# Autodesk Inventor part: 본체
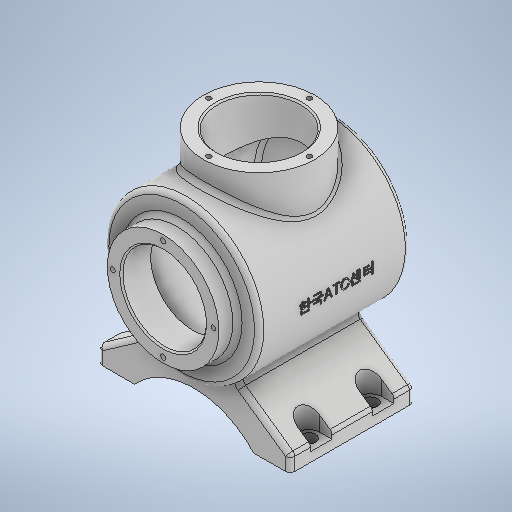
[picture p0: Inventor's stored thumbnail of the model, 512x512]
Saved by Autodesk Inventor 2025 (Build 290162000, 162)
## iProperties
Created: 2024-07
Part Number: 본체
Material: 일반
Document SubType Name: Modeling
Designer: 학생
Density: 1 g/cm^3
Appearance: 기본값
Author: 학생
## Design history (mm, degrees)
sketch "스케치1"
  geometry: C1 r 50 at (0, 0); C2 r 36 at (0, 0); 1 further point
  constraints: 2 centre point, 2 coincident
  dimensions: "d0" = 100 diameter of C1; "d3" = 72 diameter of C2
extrude "돌출1" new body sketch "스케치1" distance "d1" = 108; taper "d2" = 0 deg
fillet "모깎기1" dims "d6" = 3
sketch "스케치2"
  geometry: L1 (-50, -108)-(50, -108) reference; L2 (143.33, 5)-(-131.324, 5); L3 (-47, 0)-(47, 0) reference; L4 (113, 5)-(-113, 5); A1 r 113 centre (0, 5) between (-113, 5) and (113, 5); 2 further points
  constraints: 4 end point, 3 point on circle, 3 point on line, 1 centre point, 1 collinear, 1 midpoint, 1 parallel
  dimensions: "d8" = 113 radius of A1
revolve "회전1" sketch "스케치2" stored, may be unused: angle "d9" = 90 deg
node "작업 평면1"
feature "쉘1" dims "d33" = 7
extrude "돌출5" join sketch "스케치1" distance "d34" = 12; taper "d35" = 0 deg
sketch "스케치3"
  geometry: L1 (0, -237.107)-(0, 83.685); L2 (36, 12)-(-36, 12) reference; C1 r 36 at (0, -50); 1 further point
  constraints: 2 end point, 2 point on line, 1 centre point, 1 vertical
  dimensions: "d11" = 72 diameter of C1; "d37" = 62 distance from line of C1.centre L2
extrude "돌출3" join sketch "스케치3" stored distance "d14" = 50; taper "d15" = 0 deg
fillet "모깎기2" dims "d16" = 3
fillet "모깎기6" dims "d28" = 3
node "작업 평면3"
sketch "스케치5"
  geometry: L1 (0, 68.499)-(0, -75.315); L2 (25.101, -41.102)-(62.088, -67); L3 (62.088, -67)-(62.088, -77); L4 (62.088, -77)-(38.5, -77); L5 (-24.468, -40.658)-(-62.088, -67); L6 (-62.088, -67)-(-62.088, -77); L7 (-62.088, -77)-(-38.5, -77); C1 r 43 at (0, 0) reference; A1 r 52.096 centre (0, -112.096) between (38.5, -77) and (-38.5, -77); A2 r 72.039 centre (0.921, 26.759) between (-24.468, -40.658) and (25.101, -41.102); 2 further points
  constraints: 14 end point, 5 point on circle, 2 centre point, 2 perpendicular, 2 point on line, 2 vertical, 3 other
  dimensions: "d39" = 17 distance from line of L4 point (0, -60); "d40" = 77 distance from line of L4 point (0, 0); "d41" = 10 distance of L2.end L3.end; "d42" = 55 deg angle of L3 L2; "d43" = 77 distance of L4.end L7.end
extrude "돌출6" join sketch "스케치5" distance "d44" = 80; taper "d45" = 0 deg
sketch "스케치6"
  geometry: L1 (-38.5, 42.294)-(-38.5, -123.644); L2 (-124.405, -40)-(51.766, -40); L3 (23.588, 0)-(23.588, -80) reference; L4 (-100.588, 0)-(-100.588, -80) reference; L5 (0, 0)-(23.588, 0) reference; 7 further points
  constraints: 4 end point, 3 midpoint, 2 point on line, 2 symmetric about line, 1 horizontal, 1 vertical
  dimensions: "d53" = 108 distance of point (15.5, -20) point (-92.5, -20); "d54" = 108 distance of point (15.5, -60) point (-92.5, -60); "d55" = 40 distance of point (15.5, -60) point (15.5, -20); "d56" = 20 distance from line of point (15.5, -20) L5
hole "구멍1" sketch "스케치6" at (15.5, -20), (15.5, -60), (-92.5, -20), (-92.5, -60) diameter "d46" = 9; stored, may be unused: countersink angle "d50" = 90 deg, drill point angle "d52" = 0 deg; dims "d47" = 24, "d48" = 4, "d49" = 2, "d51" = 6
sketch "스케치7"
  geometry: C1 r 4.5 at (0, 0) reference; C2 r 4.5 at (0, -40) reference; 3 further points
  constraints: 2 coincident
hole "구멍2" sketch "스케치7" at (0, 0), (0, -40) diameter "d57" = 14; stored, may be unused: countersink angle "d61" = 90 deg, drill point angle "d63" = 0 deg; dims "d58" = 6, "d59" = 4, "d60" = 2, "d62" = 6
sketch "스케치8"
  geometry: C1 r 4.5 at (0, 0) reference; C2 r 4.5 at (0, -40) reference; 3 further points
  constraints: 2 coincident
hole "구멍3" sketch "스케치8" at (0, 0), (0, -40) diameter "d64" = 14; stored, may be unused: countersink angle "d68" = 90 deg, drill point angle "d70" = 0 deg; dims "d65" = 6, "d66" = 4, "d67" = 2, "d69" = 8
sketch "스케치9"
  geometry: L1 (-15.5, -20)-(8.088, -20) reference; L2 (-15.5, -20)-(-15.5, 60) reference; L3 (8.088, 60)-(-15.5, 60) reference; L4 (8.088, -20)-(8.088, 60) reference; L5 (-116.088, -20)-(-92.5, -20) reference; L6 (-116.088, -20)-(-116.088, 60) reference; L7 (-92.5, 60)-(-116.088, 60) reference; L8 (-92.5, -20)-(-92.5, 60) reference; L9 (28.226, -7)-(0, -7); L10 (0, -7)-(0, 7); L11 (0, 7)-(28.226, 7); L12 (28.226, 7)-(28.226, -7); L13 (31.115, 33)-(0, 33); L14 (0, 33)-(0, 47); L15 (0, 47)-(31.115, 47); L16 (31.115, 47)-(31.115, 33); L17 (-108, -7)-(-135.114, -7); L18 (-135.114, -7)-(-135.114, 7); L19 (-135.114, 7)-(-108, 7); L20 (-108, 7)-(-108, -7); L21 (-108, 33)-(-139.115, 33); L22 (-139.115, 33)-(-139.115, 47); L23 (-139.115, 47)-(-108, 47); L24 (-108, 47)-(-108, 33); C1 r 4.5 at (0, 40) reference; C2 r 4.5 at (0, 0) reference; C3 r 4.5 at (-108, 40) reference; C4 r 4.5 at (-108, 0) reference; 5 further points
  constraints: 32 end point, 8 parallel, 4 coincident, 4 horizontal, 4 midpoint, 4 perpendicular
  dimensions: "d73" = 14 distance between parallel lines of L11 L9; "d74" = 14 distance between parallel lines of L15 L13; "d75" = 14 distance between parallel lines of L19 L17; "d76" = 14 distance between parallel lines of L23 L21
extrude "돌출8" cut sketch "스케치9" distance "d77" = 20; taper "d78" = 0 deg
fillet "모깎기7" dims "d79" = 3
fillet "모깎기8" dims "d80" = 3
sketch "스케치10"
  geometry: C1 r 36 at (0, 0) reference; 2 further points
  constraints: 1 coincident
hole "구멍4" sketch "스케치10" at (0, 0) diameter "d81" = 54; stored, may be unused: countersink angle "d85" = 90 deg, drill point angle "d87" = 0 deg; dims "d82" = 6, "d83" = 4, "d84" = 2, "d86" = 19
chamfer "모따기1" distance "d88" = 1; stored, may be unused: second distance "d89" = 2, angle "d90" = 45 deg
sketch "스케치11"
  geometry: C1 r 36 at (0, 0) reference; 2 further points
  constraints: 1 coincident
hole "구멍5" sketch "스케치11" at (0, 0) diameter "d91" = 54; stored, may be unused: countersink angle "d95" = 90 deg, drill point angle "d97" = 0 deg; dims "d92" = 6, "d93" = 4, "d94" = 2, "d96" = 19
chamfer "모따기2" distance "d98" = 1; stored, may be unused: second distance "d99" = 2, angle "d100" = 45 deg
fillet "모깎기9" dims "d101" = 3
sketch "스케치12"
  geometry: L1 (0, 72.304)-(0, -92.289); L2 (-67.003, 0)-(67.003, 0); C1 r 36 at (0, 0) reference; 5 further points
  constraints: 5 point on line, 4 end point, 2 symmetric about line, 1 horizontal, 1 midpoint, 1 vertical
  dimensions: "d109" = 65 distance of point (0, -32.5) point (0, 32.5); "d110" = 65 distance of point (32.5, 0) point (-32.5, 0)
hole "구멍6" sketch "스케치12" at (0, 32.5), (-32.5, 0), (32.5, 0), (0, -32.5) diameter "d102" = 3.242; stored, may be unused: countersink angle "d106" = 90 deg, drill point angle "d108" = 118 deg; dims "d103" = 8, "d104" = 4, "d105" = 2, "d107" = 10
sketch "스케치13"
  geometry: L1 (0, 65.993)-(0, -106.174); L2 (-73.382, 0)-(92.175, 0); C1 r 36 at (0, 0) reference; 5 further points
  constraints: 6 point on line, 4 end point, 2 symmetric about line, 1 horizontal, 1 vertical
  dimensions: "d118" = 65 distance of point (0, -32.5) point (0, 32.5); "d119" = 65 distance of point (32.5, 0) point (-32.5, 0)
hole "구멍7" sketch "스케치13" at (0, 32.5), (-32.5, 0), (0, -32.5), (32.5, 0) diameter "d111" = 3.242; stored, may be unused: countersink angle "d115" = 90 deg, drill point angle "d117" = 118 deg; dims "d112" = 8, "d113" = 4, "d114" = 2, "d116" = 10
sketch "스케치14"
  geometry: L1 (-86.337, 71)-(75.152, 71); L2 (-73, 107)-(-73, 35) reference; 2 further points
  constraints: 2 end point, 2 point on line, 1 horizontal, 1 other
  dimensions: "d120" = 62 distance from line of point (-11, 71) L2
feature "엠보싱1" sketch "스케치14" dims "d121" = 0.5, "d122" = 0
node "솔리드1"
node "투영된 루프1"
node "투영된 루프2"
feature "A9D066F2-1C7D-4E18-AEED-F7BC21143FA4" dims "d46" = 9, "d47" = 24, "d48" = 4, "d49" = 2, "d50" = 90 deg, "d51" = 6, "d52" = 0
other parameters: "d10" = 65, "d29" = 0.5, "d30" = 2, "d31" = 0
